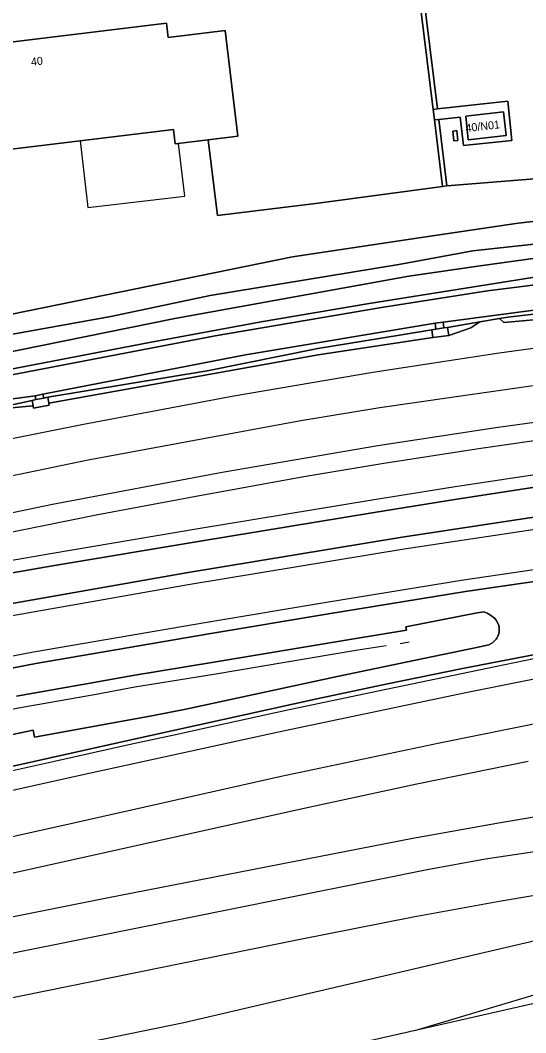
# Model space of a CAD drawing. Extents: x 161477 to 163040, y 383680 to 384871.
# Drawn here: x 162449.3 to 162512.5, y 383945.5 to 384072 of the extents above; entities that cross this region are included whole.
import ezdxf

# ---------------------------------------------------------------- set-up
doc = ezdxf.new("R2010")
doc.units = 0
for name, color, linetype in [('IMGEO_Erf', 7, 'Continuous'), ('IMGEO_Gemengd_bos', 7, 'Continuous'), ('IMGEO_Grasland_overig', 7, 'Continuous'), ('IMGEO_Groenvoorziening', 7, 'Continuous'), ('IMGEO_Haag', 7, 'Continuous'), ('IMGEO_Hek', 7, 'Continuous'), ('IMGEO_Loofbos', 7, 'Continuous'), ('IMGEO_Oever', 7, 'Continuous'), ('IMGEO_Pand', 7, 'Continuous'), ('IMGEO_Pand_nummerreeks', 7, 'Continuous'), ('IMGEO_Perron', 7, 'Continuous'), ('IMGEO_Spoor', 7, 'Continuous'), ('IMGEO_Spoorbaan_halfverhard', 7, 'Continuous'), ('IMGEO_Terreindeel_gesloten', 7, 'Continuous'), ('IMGEO_Terreindeel_onvherhard', 7, 'Continuous'), ('IMGEO_Voetpad_op_trap', 7, 'Continuous'), ('IMGEO_Voetpad_open', 7, 'Continuous'), ('IMGEO_Waterloop', 7, 'Continuous')]:
    doc.layers.add(name, color=color, linetype=linetype)

msp = doc.modelspace()

# ---------------------------------------------------------------- linework, layer by layer
at = {"layer": 'IMGEO_Erf'}
msp.add_lwpolyline([(162434.77, 384067.08), (162434.7, 384067.6), (162467.57, 384071.6), (162467.78, 384069.81), (162474.92, 384070.68), (162476.52, 384057.46), (162472.78, 384057.01), (162473.95, 384047.55), (162486.52, 384049.09), (162502.09, 384051.2), (162501.07, 384059.53), (162500.91, 384060.82), (162498.63, 384079.4)], dxfattribs=at)
at = {"layer": 'IMGEO_Gemengd_bos'}
msp.add_lwpolyline([(162633.88, 384061.75), (162502.61, 384051.26), (162502.09, 384051.2), (162486.52, 384049.09), (162473.95, 384047.55), (162472.78, 384057.01), (162468.68, 384056.51), (162468.46, 384058.3), (162442.36, 384055.14), (162443.66, 384044.4), (162435.42, 384043.41), (162435.96, 384037.39), (162431.71, 384036.49), (162422.35, 384034.5), (162418.45, 384034.03), (162406.67, 384032.62), (162396.82, 384031.44), (162397.69, 384024.41), (162403.09, 384025.61), (162446.18, 384034.84), (162483.35, 384042.4), (162500, 384044.89), (162511.54, 384046.62), (162535.75, 384049.36)], dxfattribs=at)
at = {"layer": 'IMGEO_Grasland_overig'}
for points in [[(162516.99, 384040.41), (162492.9, 384036.58), (162479.42, 384034.28), (162465.46, 384031.71), (162428.2, 384024.54), (162417.06, 384021.91), (162399.08, 384018), (162386.42, 384015.02), (162348.52, 384007.18), (162336.74, 384004.62), (162319.36, 384000.44), (162306.41, 383997.6), (162289.61, 383993.74), (162277.97, 383991.3), (162261.88, 383987.71), (162250.15, 383985.41), (162230.73, 383980.85), (162207.55, 383975.75)], [(162209.37, 383975.39), (162244.66, 383983.25), (162282.78, 383991.27), (162306.35, 383997.16), (162319.02, 384000.06), (162336.64, 384003.73), (162362.3, 384009.07), (162386.31, 384014.48), (162405.43, 384018.65), (162413.58, 384020.62), (162434.97, 384025.14), (162473.66, 384032.52), (162494.44, 384036.08), (162507.7, 384038.18), (162528.6, 384040.8)]]:
    msp.add_lwpolyline(points, dxfattribs=at)
for points in [[(162536.13, 384038.46), (162514.45, 384035.89), (162502.14, 384034.26), (162502.24, 384033.53), (162502.72, 384033.59), (162506.76, 384034.28), (162509.19, 384034.69), (162510.26, 384034.87), (162536.22, 384037.88), (162548.05, 384039.31), (162551.62, 384039.74), (162552.1, 384039.79), (162552.02, 384040.52)], [(162551.62, 384039.74), (162548.05, 384039.31), (162536.22, 384037.88), (162510.26, 384034.87), (162509.19, 384034.69), (162509.73, 384034.19), (162515.31, 384034.72), (162531.04, 384036.83), (162540.02, 384037.8), (162551.69, 384039.02)], [(162452.15, 384025.24), (162452.24, 384024.77), (162452.74, 384024.86), (162472.68, 384028.17), (162486.48, 384030.95), (162494.18, 384032.2), (162500.74, 384033.31), (162501.25, 384033.39), (162501.15, 384034.12), (162477.46, 384030.17)], [(162502.72, 384033.59), (162502.86, 384032.6), (162505.63, 384033.52), (162506.76, 384034.28)], [(162494.18, 384032.2), (162486.48, 384030.95), (162472.68, 384028.17), (162452.74, 384024.86), (162452.88, 384024.15), (162486.53, 384030.16), (162500.88, 384032.32), (162500.74, 384033.31)], [(162434.73, 384021.53), (162435.99, 384021.89), (162447.12, 384023.66), (162450.78, 384024.48), (162451.26, 384024.58), (162451.17, 384025.05), (162446.45, 384024.42), (162437.45, 384022.77), (162401.99, 384015.08), (162402.14, 384014.22), (162402.68, 384014.31), (162412.07, 384016.3), (162430.87, 384020.43)], [(162447.12, 384023.66), (162435.99, 384021.89), (162437.49, 384021.62), (162444.25, 384022.73), (162447.77, 384023.5), (162450.91, 384023.79), (162450.78, 384024.48)]]:
    msp.add_lwpolyline(points, close=True, dxfattribs=at)
at = {"layer": 'IMGEO_Groenvoorziening'}
msp.add_lwpolyline([(162479.57, 384081.23), (162479.83, 384078.77), (162480.44, 384078.82), (162480.18, 384081.15), (162498.16, 384083.29), (162498.63, 384079.4), (162500.91, 384060.82), (162501.44, 384060.88), (162499.18, 384079.48)], dxfattribs=at)
msp.add_lwpolyline([(162501.6, 384059.58), (162501.07, 384059.53), (162502.09, 384051.2), (162502.61, 384051.26)], close=True, dxfattribs=at)
at = {"layer": 'IMGEO_Haag'}
msp.add_lwpolyline([(162479.57, 384081.23), (162479.83, 384078.77), (162480.44, 384078.82), (162480.18, 384081.15), (162498.16, 384083.29), (162498.63, 384079.4), (162500.91, 384060.82), (162501.44, 384060.88), (162499.18, 384079.48)], dxfattribs=at)
msp.add_lwpolyline([(162501.6, 384059.58), (162501.07, 384059.53), (162502.09, 384051.2), (162502.61, 384051.26)], close=True, dxfattribs=at)
at = {"layer": 'IMGEO_Hek'}
for points in [[(162456.8, 384056.89), (162457.75, 384048.56)], [(162469.87, 384049.97), (162469.08, 384056.56)], [(162457.75, 384048.56), (162469.87, 384049.97)], [(162516.74, 384019.88), (162506.87, 384018.46), (162494.51, 384016.55), (162484.75, 384014.94), (162471.06, 384012.45), (162458.79, 384010.15), (162442.73, 384006.91), (162420.74, 384002.28), (162415.83, 384001.21), (162410.98, 384000.19), (162393.96, 383996.37), (162384.18, 383994.21), (162362.25, 383989.37), (162337.86, 383983.98), (162284.26, 383972.05), (162262.3, 383967.18), (162247.59, 383963.84), (162240.29, 383962.24), (162220.89, 383958)], [(162423.74, 383973.28), (162423.94, 383972.92), (162423.98, 383972.84), (162426.78, 383973.47), (162427.89, 383973.71), (162432.06, 383974.64), (162436.24, 383975.58), (162440.77, 383976.59), (162445.31, 383977.59), (162452.45, 383979.15), (162453.61, 383979.42), (162458.43, 383980.49), (162463.25, 383981.56), (162468.34, 383982.67), (162473.43, 383983.78), (162482.93, 383985.85), (162484.13, 383986.12), (162489.08, 383987.16), (162494.04, 383988.21), (162508.67, 383991.23), (162511.08, 383991.72), (162513.51, 383992.22)]]:
    msp.add_lwpolyline(points, dxfattribs=at)
at = {"layer": 'IMGEO_Loofbos'}
msp.add_lwpolyline([(162617.7, 384104.58), (162619.03, 384099.85), (162598.59, 384089.27), (162593.45, 384085.13), (162589.3, 384083.7), (162583.59, 384084.27), (162568.3, 384089.13), (162499.18, 384079.48), (162501.44, 384060.88), (162510.24, 384061.84), (162510.76, 384056.94), (162504.7, 384056.3), (162504.28, 384059.87), (162501.6, 384059.58), (162502.61, 384051.26), (162633.88, 384061.75)], dxfattribs=at)
msp.add_lwpolyline([(162503.99, 384056.94), (162503.5, 384056.88), (162503.36, 384058.12), (162503.85, 384058.18)], close=True, dxfattribs=at)
at = {"layer": 'IMGEO_Oever'}
for points in [[(162535.75, 384049.36), (162511.54, 384046.62), (162500, 384044.89), (162483.35, 384042.4), (162446.18, 384034.84), (162403.09, 384025.61), (162397.69, 384024.41), (162372.83, 384018.9), (162343.86, 384012.47), (162335.03, 384010.3), (162316.33, 384006.26), (162312.37, 384005.4), (162287.46, 384000), (162255.54, 383993.14), (162233.3, 383987.99), (162225.18, 383986.05)], [(162225.31, 383985.64), (162245.94, 383990.07), (162283.16, 383996.91), (162313.36, 384003.26), (162344.28, 384010.17), (162365.88, 384014.72), (162413.83, 384025.55), (162446.02, 384032.35), (162460.63, 384034.96), (162473.04, 384037.58), (162496.6, 384041.44), (162505.86, 384043.17), (162533.72, 384046.18)], [(162528.42, 384044.29), (162506.78, 384041.3), (162497.86, 384040), (162468.63, 384034.71), (162446.2, 384030.16), (162422.6, 384025.23), (162394.8, 384019.25), (162368.43, 384013.24), (162357.1, 384010.52), (162346.49, 384008.14), (162319.82, 384002.27), (162308.86, 384000.2), (162290.05, 383995.51), (162270.87, 383991.27), (162258.55, 383988.91), (162252.95, 383987.62), (162241.86, 383985.28), (162220.27, 383980.56)], [(162207.55, 383975.75), (162230.73, 383980.85), (162250.15, 383985.41), (162261.88, 383987.71), (162277.97, 383991.3), (162289.61, 383993.74), (162306.41, 383997.6), (162319.36, 384000.44), (162336.74, 384004.62), (162348.52, 384007.18), (162386.42, 384015.02), (162399.08, 384018), (162417.06, 384021.91), (162428.2, 384024.54), (162465.46, 384031.71), (162479.42, 384034.28), (162492.9, 384036.58), (162516.99, 384040.41)]]:
    msp.add_lwpolyline(points, dxfattribs=at)
at = {"layer": 'IMGEO_Pand'}
for points in [[(162427.5, 384063.07), (162424.39, 384062.69), (162421.19, 384062.31), (162410.13, 384060.97), (162411.72, 384047.8), (162426.73, 384049.61), (162426.33, 384052.96), (162429.18, 384053.3), (162430.46, 384042.8), (162435.42, 384043.41), (162443.66, 384044.4), (162442.36, 384055.14), (162468.46, 384058.3), (162468.68, 384056.51), (162472.78, 384057.01), (162476.52, 384057.46), (162474.92, 384070.68)], [(162474.92, 384070.68), (162467.78, 384069.81), (162467.57, 384071.6), (162434.7, 384067.6), (162434.77, 384067.08)]]:
    msp.add_lwpolyline(points, dxfattribs=at)
msp.add_lwpolyline([(162509.69, 384060.51), (162504.98, 384059.97), (162505.29, 384057.02), (162510.02, 384057.57)], close=True, dxfattribs=at)
at = {"layer": 'IMGEO_Perron'}
for points in [[(162517.14, 384014.16), (162503.88, 384012.15), (162493.53, 384010.49), (162471.81, 384006.9), (162453.35, 384003.8), (162448.09, 384002.88), (162438.9, 384001.21), (162422.71, 383998.11), (162410.23, 383995.58), (162392.86, 383991.85), (162384.61, 383990.02), (162368.82, 383986.53), (162353.59, 383983.12), (162331.38, 383978.2), (162301.8, 383971.65), (162274.55, 383965.55), (162267.33, 383963.92), (162236.4, 383957.04), (162205.25, 383950.14)], [(162200.54, 383944.9), (162249.03, 383955.68), (162272.7, 383960.93), (162284.64, 383963.58), (162335.8, 383974.9), (162361.71, 383980.64), (162387.8, 383986.4), (162414.54, 383992.33), (162441.39, 383997.91), (162470.06, 384002.95), (162497.05, 384007.41), (162522.84, 384011.3)], [(162527.02, 384003.82), (162504.95, 384000.61), (162487.83, 383997.8), (162472.86, 383995.32), (162451.24, 383991.62), (162434.8, 383988.45), (162424.78, 383986.35), (162418.26, 383984.93), (162407.38, 383982.5), (162388.62, 383978.39), (162368.24, 383973.86), (162358.92, 383971.78), (162345.66, 383968.85), (162332.99, 383966.04), (162311.47, 383961.27), (162301.08, 383958.97), (162282.23, 383954.81), (162265.73, 383951.15), (162253.49, 383948.43), (162230.94, 383943.46), (162221.43, 383941.34)], [(162448.84, 383987.53), (162458.52, 383989.24), (162463.38, 383990.13), (162473.52, 383991.78), (162491.01, 383994.7), (162497.57, 383995.76), (162497.51, 383996.2), (162506.39, 383997.93), (162507.28, 383998.05), (162507.64, 383997.92), (162507.86, 383997.79), (162508.09, 383997.63), (162508.57, 383997.27), (162508.78, 383997.02), (162508.96, 383996.73), (162509.11, 383996.38), (162509.14, 383996.06), (162509.16, 383995.85), (162509.16, 383995.54), (162509.08, 383995.24), (162508.99, 383995.02), (162508.87, 383994.79), (162508.8, 383994.66), (162508.62, 383994.47), (162508.32, 383994.21), (162507.85, 383993.93), (162505.96, 383993.54), (162499.7, 383992.24), (162489.14, 383990.05), (162469.99, 383985.92), (162465.98, 383985.13), (162451.08, 383982.42), (162450.93, 383983.3), (162446.98, 383982.46)], [(162447.83, 383978.66), (162462.57, 383981.95), (162486.36, 383987.2), (162495.21, 383989.09), (162504.59, 383991), (162521.67, 383994.29)]]:
    msp.add_lwpolyline(points, dxfattribs=at)
at = {"layer": 'IMGEO_Spoor'}
for points in [[(162525.34, 384032.6), (162509.14, 384030.36), (162493.36, 384027.95), (162475.98, 384025), (162457.2, 384021.48), (162440.93, 384018.2), (162423.7, 384014.55), (162401.26, 384009.64), (162149.2, 383953.57)], [(162517.19, 384026.84), (162503.19, 384024.85), (162494.26, 384023.53), (162484.38, 384021.92), (162457.8, 384017.03), (162430.46, 384011.36), (162185.95, 383957.04), (162177.81, 383955.39), (162172.86, 383954.55), (162165.75, 383953.57), (162149.65, 383951.79)], [(162522.91, 384023.02), (162508.75, 384021.06), (162493.98, 384018.8), (162474.53, 384015.47), (162453.35, 384011.49), (162424.4, 384005.42), (162363.11, 383991.88), (162319.76, 383982.15), (162259.18, 383968.95), (162197.14, 383955.06)], [(162516.93, 384015.68), (162503.64, 384013.67), (162493.28, 384012.02), (162471.56, 384008.42), (162453.09, 384005.32), (162447.82, 384004.39), (162438.62, 384002.73), (162422.41, 383999.62), (162409.91, 383997.09), (162392.54, 383993.36), (162384.28, 383991.52), (162368.49, 383988.03), (162353.25, 383984.63), (162331.04, 383979.7), (162301.46, 383973.15), (162274.22, 383967.05), (162266.99, 383965.42), (162236.06, 383958.54), (162204.92, 383951.64), (162178.16, 383945.64), (162141.24, 383937.49), (162121.53, 383933.06), (162112.43, 383931.11)], [(162112.31, 383923.94), (162128.77, 383927.61), (162135.63, 383929.04), (162172.67, 383937.27), (162200.86, 383943.44), (162249.36, 383954.22), (162273.02, 383959.47), (162284.97, 383962.12), (162336.13, 383973.44), (162362.03, 383979.17), (162388.12, 383984.93), (162414.86, 383990.86), (162441.68, 383996.44), (162470.31, 384001.47), (162497.28, 384005.93), (162523.05, 384009.81)], [(162526.83, 384005.25), (162504.72, 384002.04), (162487.59, 383999.23), (162472.62, 383996.75), (162450.98, 383993.05), (162434.51, 383989.87), (162424.48, 383987.77), (162417.95, 383986.35), (162407.06, 383983.91), (162388.31, 383979.81), (162367.93, 383975.28), (162358.6, 383973.2), (162345.34, 383970.27), (162332.68, 383967.46), (162300.77, 383960.39), (162281.92, 383956.23), (162265.41, 383952.57), (162253.18, 383949.85), (162230.62, 383944.88), (162221.12, 383942.75)], [(162495.04, 383993.83), (162491.25, 383993.22), (162473.77, 383990.3), (162463.63, 383988.65), (162458.78, 383987.76), (162449.11, 383986.05), (162440.29, 383984.34), (162430.81, 383982.42), (162410.65, 383978.07), (162402.6, 383976.26), (162383.78, 383972.09), (162363.97, 383967.74), (162358.73, 383966.55), (162331.72, 383960.58), (162317.93, 383957.54), (162301.02, 383953.79), (162266.3, 383946.08), (162230.88, 383938.25), (162187.27, 383928.57), (162172.27, 383925.27), (162156.76, 383921.84), (162138.64, 383917.89), (162133.33, 383916.82)], [(162496.77, 383994.11), (162497.93, 383994.3)], [(161983.02, 383882.43), (162002.6, 383886.8), (162017.08, 383889.7), (162027.28, 383891.57), (162036.3, 383892.96), (162053.1, 383895.33), (162060.81, 383896.33), (162085.72, 383899.26), (162099.11, 383900.95), (162110.01, 383902.48), (162119.36, 383903.88), (162127.92, 383905.34), (162136.6, 383906.89), (162146.67, 383908.84), (162166.54, 383913.05), (162267.83, 383935.63), (162298.18, 383942.49), (162368.54, 383958.02), (162456.6, 383977.62), (162481.58, 383983.09), (162504.99, 383988.01), (162523.58, 383991.7)], [(162658.61, 383987.28), (162550.15, 383977.06), (162535.61, 383975.61), (162528.29, 383974.72), (162518.98, 383973.34), (162509.32, 383971.71), (162498.36, 383969.74), (162460.12, 383962.29), (162429.04, 383956.1), (162421.53, 383954.44), (162414.59, 383952.68), (162407.04, 383950.34), (162402.59, 383948.85)], [(162515.55, 383984.45), (162501.71, 383981.65), (162481.93, 383977.52), (162456.16, 383971.71), (162431.85, 383966.32), (162359.57, 383950.27)], [(162512.77, 383979.39), (162498.88, 383976.53), (162484.2, 383973.38), (162329.8, 383939.06)], [(162614.99, 383978.19), (162567.08, 383973.75), (162529.43, 383970.12), (162517.21, 383968.64), (162507.43, 383967.16), (162500.17, 383965.83), (162427.93, 383951.32), (162403.28, 383946.16)], [(162572.53, 383968.93), (162535.49, 383965.56), (162525.58, 383964.43), (162518.06, 383963.37), (162509.41, 383961.94), (162498.43, 383959.92), (162484.09, 383957.11), (162403.16, 383940.69)], [(162521.87, 383958.89), (162469.77, 383946.74), (162455.91, 383943.91), (162448.06, 383942.59), (162439.39, 383941.39), (162432.15, 383940.56), (162422.33, 383939.59)], [(162526.27, 383954.03), (162498.87, 383945.83)], [(162526.75, 383952.14), (162498.87, 383945.83)], [(162498.87, 383945.83), (162489.11, 383943.6)]]:
    msp.add_lwpolyline(points, dxfattribs=at)
at = {"layer": 'IMGEO_Spoorbaan_halfverhard'}
for points in [[(162515.31, 384034.72), (162509.73, 384034.19), (162509.19, 384034.69), (162506.76, 384034.28), (162505.63, 384033.52), (162502.86, 384032.6), (162500.88, 384032.32), (162486.53, 384030.16), (162452.88, 384024.15), (162452.93, 384023.88), (162450.97, 384023.5), (162450.91, 384023.79), (162447.77, 384023.5)], [(162205.25, 383950.14), (162236.4, 383957.04), (162267.33, 383963.92), (162274.55, 383965.55), (162301.8, 383971.65), (162331.38, 383978.2), (162353.59, 383983.12), (162368.82, 383986.53), (162384.61, 383990.02), (162392.86, 383991.85), (162410.23, 383995.58), (162422.71, 383998.11), (162438.9, 384001.21), (162448.09, 384002.88), (162453.35, 384003.8), (162471.81, 384006.9), (162493.53, 384010.49), (162503.88, 384012.15), (162517.14, 384014.16)], [(162522.84, 384011.3), (162497.05, 384007.41), (162470.06, 384002.95), (162441.39, 383997.91), (162414.54, 383992.33), (162387.8, 383986.4), (162361.71, 383980.64), (162335.8, 383974.9), (162284.64, 383963.58), (162272.7, 383960.93), (162249.03, 383955.68), (162200.54, 383944.9)], [(162221.43, 383941.34), (162230.94, 383943.46), (162253.49, 383948.43), (162265.73, 383951.15), (162282.23, 383954.81), (162301.08, 383958.97), (162311.47, 383961.27), (162332.99, 383966.04), (162345.66, 383968.85), (162358.92, 383971.78), (162368.24, 383973.86), (162388.62, 383978.39), (162407.38, 383982.5), (162418.26, 383984.93), (162424.78, 383986.35), (162434.8, 383988.45), (162451.24, 383991.62), (162472.86, 383995.32), (162487.83, 383997.8), (162504.95, 384000.61), (162527.02, 384003.82)], [(162446.98, 383982.46), (162450.93, 383983.3), (162451.08, 383982.42), (162465.98, 383985.13), (162469.99, 383985.92), (162489.14, 383990.05), (162499.7, 383992.24), (162505.96, 383993.54), (162507.85, 383993.93), (162508.32, 383994.21), (162508.62, 383994.47), (162508.8, 383994.66), (162508.87, 383994.79), (162508.99, 383995.02), (162509.08, 383995.24), (162509.16, 383995.54), (162509.16, 383995.85), (162509.14, 383996.06), (162509.11, 383996.38), (162508.96, 383996.73), (162508.78, 383997.02), (162508.57, 383997.27), (162508.09, 383997.63), (162507.86, 383997.79), (162507.64, 383997.92), (162507.28, 383998.05), (162506.39, 383997.93), (162497.51, 383996.2), (162497.57, 383995.76), (162491.01, 383994.7), (162473.52, 383991.78), (162463.38, 383990.13), (162458.52, 383989.24), (162448.84, 383987.53)], [(162521.67, 383994.29), (162504.59, 383991), (162495.21, 383989.09), (162486.36, 383987.2), (162462.57, 383981.95), (162447.83, 383978.66)]]:
    msp.add_lwpolyline(points, dxfattribs=at)
at = {"layer": 'IMGEO_Terreindeel_gesloten'}
for points in [[(162503.99, 384056.94), (162503.85, 384058.18), (162503.36, 384058.12), (162503.5, 384056.88)], [(162502.24, 384033.53), (162501.25, 384033.39), (162500.74, 384033.31), (162500.88, 384032.32), (162502.86, 384032.6), (162502.72, 384033.59)], [(162452.74, 384024.86), (162452.24, 384024.77), (162451.26, 384024.58), (162450.78, 384024.48), (162450.91, 384023.79), (162450.97, 384023.5), (162452.93, 384023.88), (162452.88, 384024.15)]]:
    msp.add_lwpolyline(points, close=True, dxfattribs=at)
at = {"layer": 'IMGEO_Terreindeel_onvherhard'}
for points in [[(162528.6, 384040.8), (162507.7, 384038.18), (162494.44, 384036.08), (162473.66, 384032.52), (162434.97, 384025.14), (162413.58, 384020.62), (162405.43, 384018.65), (162386.31, 384014.48), (162362.3, 384009.07), (162336.64, 384003.73), (162319.02, 384000.06), (162306.35, 383997.16), (162282.78, 383991.27), (162244.66, 383983.25), (162209.37, 383975.39)], [(162355.4, 384005.04), (162366.9, 384007.66), (162374.64, 384009.29), (162379.78, 384010.28), (162396.8, 384014.02), (162401.01, 384014.91), (162401.99, 384015.08), (162437.45, 384022.77), (162446.45, 384024.42), (162451.17, 384025.05), (162452.15, 384025.24), (162477.46, 384030.17), (162501.15, 384034.12), (162502.14, 384034.26), (162514.45, 384035.89)]]:
    msp.add_lwpolyline(points, dxfattribs=at)
at = {"layer": 'IMGEO_Voetpad_op_trap'}
for points in [[(162501.15, 384034.12), (162501.25, 384033.39), (162502.24, 384033.53), (162502.14, 384034.26)], [(162451.17, 384025.05), (162451.26, 384024.58), (162452.24, 384024.77), (162452.15, 384025.24)]]:
    msp.add_lwpolyline(points, close=True, dxfattribs=at)
at = {"layer": 'IMGEO_Voetpad_open'}
for points in [[(162510.24, 384061.84), (162501.44, 384060.88), (162500.91, 384060.82), (162501.07, 384059.53), (162501.6, 384059.58), (162504.28, 384059.87), (162504.7, 384056.3), (162510.76, 384056.94)], [(162504.98, 384059.97), (162509.69, 384060.51), (162510.02, 384057.57), (162505.29, 384057.02)]]:
    msp.add_lwpolyline(points, close=True, dxfattribs=at)
at = {"layer": 'IMGEO_Waterloop'}
for points in [[(162533.72, 384046.18), (162505.86, 384043.17), (162496.6, 384041.44), (162473.04, 384037.58), (162460.63, 384034.96), (162446.02, 384032.35), (162413.83, 384025.55), (162365.88, 384014.72), (162344.28, 384010.17), (162313.36, 384003.26), (162283.16, 383996.91), (162245.94, 383990.07), (162225.31, 383985.64)], [(162220.27, 383980.56), (162241.86, 383985.28), (162252.95, 383987.62), (162258.55, 383988.91), (162270.87, 383991.27), (162290.05, 383995.51), (162308.86, 384000.2), (162319.82, 384002.27), (162346.49, 384008.14), (162357.1, 384010.52), (162368.43, 384013.24), (162394.8, 384019.25), (162422.6, 384025.23), (162446.2, 384030.16), (162468.63, 384034.71), (162497.86, 384040), (162506.78, 384041.3), (162528.42, 384044.29)]]:
    msp.add_lwpolyline(points, dxfattribs=at)

# ---------------------------------------------------------------- texts
at = {"layer": 'IMGEO_Pand_nummerreeks'}
for s, rotation, p in [('40', 6.9442, (162450.71, 384066.25)), ('40/N01', 6.5088, (162505.01, 384057.98))]:
    msp.add_text(s, height=1, rotation=rotation, dxfattribs=at).set_placement(p)

doc.saveas('drawing.dxf')
